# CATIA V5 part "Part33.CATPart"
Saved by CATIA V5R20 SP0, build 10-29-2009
Part number: 9TS2008M8
Revision: ANY
Definition: UNKNOWN
Nomenclature: 9TS2008M8
Source: Unknown
Bounding box of the stored display mesh (mm): x -10 to 10, y -10 to 10, z 0 to 8
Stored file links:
  C:\Users\Utente\Desktop\IO LAVORO\3D X SITO CF\CUMSA\3D files GR\GR 424546-15\Part33.CATPart
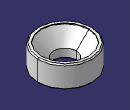
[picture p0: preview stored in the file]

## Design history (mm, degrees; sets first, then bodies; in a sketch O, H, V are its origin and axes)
Body1 "Chaflán1" (main body)
  Solid1: solid without history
